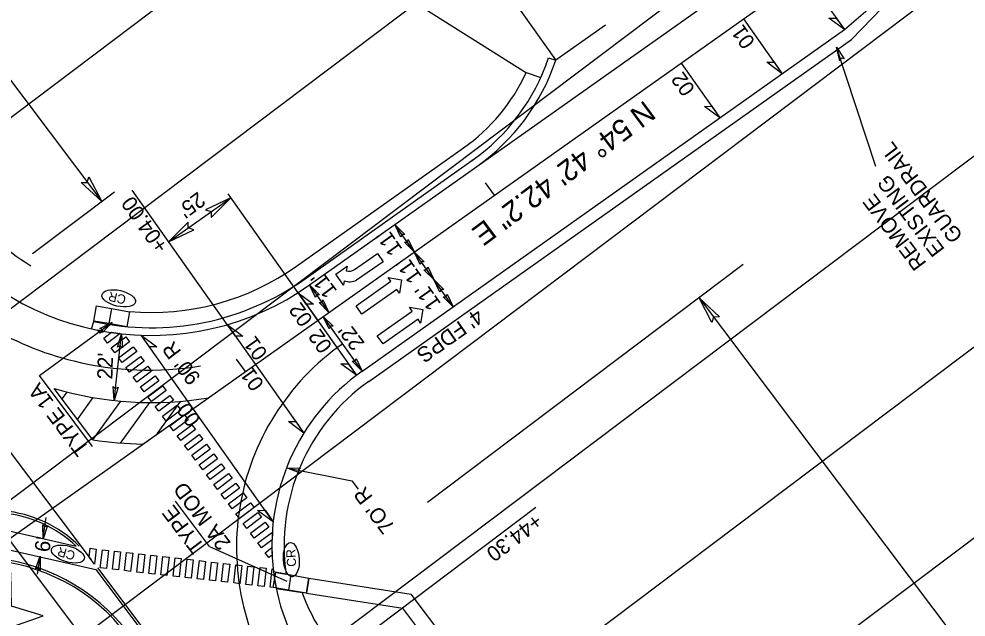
# Model space of a CAD drawing. Extents: x 1262309 to 1264352, y 775189 to 777755.
# Drawn here: x 1263383.2 to 1263693.6, y 776538.6 to 776734.6 of the extents above; entities that cross this region are included whole.
import ezdxf

# ---------------------------------------------------------------- set-up
doc = ezdxf.new("R2010")
doc.units = 0
for name, color, linetype in [('Default', 7, 'Continuous'), ('Old_Level_2', 7, 'Continuous'), ('Prop Conc 2ft 6in Curb and Gutter', 7, 'Continuous'), ('Prop Conc 4in Sidewalk', 7, 'Continuous'), ('Prop Conc 5in Monolithic Keyed In Island', 7, 'Continuous'), ('Prop Dimension', 7, 'Continuous'), ('Prop Dimension Text', 7, 'Continuous'), ('Prop EOT', 7, 'Continuous'), ('Prop Horizontal Alignment', 7, 'Continuous'), ('Prop Horizontal Alignment Direction Label', 7, 'Continuous'), ('Prop Horizontal Alignment Tick Small', 7, 'Continuous'), ('Prop Lane Arrow CELL', 7, 'Continuous'), ('Prop Lane Lines', 7, 'Continuous'), ('Prop Mkg Solid White Crosswalks', 7, 'Continuous'), ('Prop Paint Stripe', 7, 'Continuous'), ('Prop Paved Shoulder', 7, 'Continuous'), ('Prop RDY Traffic Signal CELL', 7, 'Continuous'), ('Prop Superelevation  Arrow CELL', 7, 'Continuous'), ('Prop Superelevation Label', 7, 'Continuous'), ('Prop Terminator CELL', 7, 'Continuous'), ('Scratch_Level_3', 7, 'Continuous'), ('Scratch_Level_5', 7, 'Continuous')]:
    doc.layers.add(name, color=color, linetype=linetype)

msp = doc.modelspace()

# ---------------------------------------------------------------- linework, layer by layer
at = {"layer": 'Default'}
for centre, major_axis in [((1263415.87, 776643.06), (-5.47, 1.25)), ((1263399.22, 776559.25), (-5.38, 1.6)), ((1263472.45, 776557.44), (-0.35, 5.6))]:
    msp.add_ellipse(centre, major_axis=major_axis, ratio=0.462467, dxfattribs=at)
at = {"layer": 'Old_Level_2'}
for p, q in [((1263407.74, 776635.62), (1263408.59, 776640.54)), ((1263408.59, 776640.54), (1263413.51, 776639.69)), ((1263413.51, 776639.69), (1263412.66, 776634.77)), ((1263413.51, 776639.69), (1263419.43, 776638.68)), ((1263419.43, 776638.68), (1263418.58, 776633.75)), ((1263412.66, 776634.77), (1263407.74, 776635.62)), ((1263418.58, 776633.75), (1263412.66, 776634.77)), ((1263466.55, 776548.32), (1263467.4, 776553.24)), ((1263467.4, 776553.24), (1263472.33, 776552.4)), ((1263472.33, 776552.4), (1263471.48, 776547.47)), ((1263472.33, 776552.4), (1263478.24, 776551.38)), ((1263478.24, 776551.38), (1263477.39, 776546.45)), ((1263471.48, 776547.47), (1263466.55, 776548.32)), ((1263477.39, 776546.45), (1263471.48, 776547.47))]:
    msp.add_line(p, q, dxfattribs=at)
at = {"layer": 'Prop Conc 2ft 6in Curb and Gutter'}
for p, q in [((1263556.78, 776721.9), (1263559.15, 776721.1)), ((1263477, 776649.47), (1263534.29, 776690.02)), ((1263406.99, 776633.03), (1263407.7, 776635.43))]:
    msp.add_line(p, q, dxfattribs=at)
for centre, radius, start, end in [((1263492.78, 776743.34), 67.5, 305.2882, 341.4806), ((1263426.45, 776720.9), 87.5, 257.6223, 305.2883)]:
    msp.add_arc(centre, radius, start, end, dxfattribs=at)
at = {"layer": 'Prop Conc 4in Sidewalk'}
for p, q in [((1263549.46, 776717.01), (1263554.21, 776715.37)), ((1263474.11, 776653.56), (1263528.88, 776692.32)), ((1263352.07, 776573.23), (1263401.96, 776561.79)), ((1263357.74, 776565.71), (1263408.37, 776554.17)), ((1263477.39, 776546.45), (1263478.16, 776551.39)), ((1263478.16, 776551.39), (1263511.75, 776546.15)), ((1263482.7, 776550.68), (1263482.7, 776550.68)), ((1263477.39, 776546.45), (1263508.98, 776541.52)), ((1263631.62, 776387.01), (1263511.75, 776546.15)), ((1263627.63, 776384), (1263508.98, 776541.52))]:
    msp.add_line(p, q, dxfattribs=at)
for centre, radius, start, end in [((1263492.78, 776743.34), 62.5, 305.2882, 335.0887), ((1263426.45, 776720.9), 82.5, 265.1157, 305.2883)]:
    msp.add_arc(centre, radius, start, end, dxfattribs=at)
at = {"layer": 'Prop Conc 5in Monolithic Keyed In Island'}
msp.add_line((1263408.37, 776554.17), (1263476.42, 776463.84), dxfattribs=at)
for centre, radius, start, end in [((1263374.37, 776532.83), 40, 46.384, 84.7486), ((1263368.91, 776495.2), 63, 36.9874, 86.8533)]:
    msp.add_arc(centre, radius, start, end, dxfattribs=at)
at = {"layer": 'Prop Dimension'}
for p, q in [((1263199.74, 776954.3), (1263410.31, 776674.73)), ((1263531.55, 776760.08), (1263559.04, 776721.24)), ((1263451.43, 776634.43), (1263420.26, 776678.47)), ((1263432.22, 776661.58), (1263452.62, 776676.02)), ((1263474.65, 776644.89), (1263451.74, 776677.26)), ((1263512.77, 776658.25), (1263506.42, 776667.23)), ((1263519.18, 776649.2), (1263512.77, 776658.25)), ((1263620.57, 776654.09), (1263517.13, 776576.18)), ((1263525.48, 776640.3), (1263519.18, 776649.2)), ((1263606.13, 776643.21), (1263816.71, 776363.63)), ((1263495.65, 776619.18), (1263482.94, 776637.14)), ((1263414.4, 776609.55), (1263416.77, 776631.42)), ((1263470.88, 776587.53), (1263492.31, 776583.24)), ((1263492.31, 776583.24), (1263494.35, 776580.54)), ((1263552.6, 776574.48), (1263437.44, 776487.74)), ((1263391.18, 776565.46), (1263392.08, 776571.21)), ((1263389.21, 776552.68), (1263390.1, 776558.41))]:
    msp.add_line(p, q, dxfattribs=at)
at = {"layer": 'Prop Dimension Text'}
for p, q in [((1263509.79, 776742.02), (1263549.53, 776716.98)), ((1263414.46, 776677.86), (1263387.59, 776657.62)), ((1263478.44, 776647.43), (1263484.8, 776638.46)), ((1263389.86, 776617.77), (1263413.72, 776635.21)), ((1263407.33, 776594.49), (1263389.86, 776617.77)), ((1263445.65, 776561.73), (1263434.5, 776576.6)), ((1263445.65, 776561.73), (1263470.95, 776550.38))]:
    msp.add_line(p, q, dxfattribs=at)
msp.add_lwpolyline([(1263664.08, 776686.26), (1263651.21, 776725.38)], dxfattribs=at)
for points in [[(1263406.13, 776682.85), (1263410.31, 776674.73), (1263403.59, 776681), (1263405.56, 776681.04)], [(1263446.17, 776669.55), (1263452.62, 776676.02), (1263444.31, 776672.1), (1263446.17, 776671.45)], [(1263438.67, 776668.04), (1263432.22, 776661.58), (1263440.53, 776665.5), (1263438.67, 776666.14)], [(1263610.3, 776635.09), (1263606.13, 776643.21), (1263612.85, 776636.94), (1263610.88, 776636.9)], [(1263409.65, 776633.15), (1263413.72, 776635.21), (1263410.57, 776631.87), (1263410.55, 776632.85)]]:
    msp.add_lwpolyline(points, close=True, dxfattribs=at)
at = {"layer": 'Prop EOT'}
for p, q in [((1263653.77, 776731.09), (1263672.75, 776747.55)), ((1263575.42, 776732.61), (1263559.15, 776721.1)), ((1263495.54, 776619.1), (1263653.77, 776731.09)), ((1263478.44, 776647.43), (1263533.22, 776686.2)), ((1263408.87, 776554.75), (1263477.01, 776464.29))]:
    msp.add_line(p, q, dxfattribs=at)
for centre, radius, start, end in [((1263492.78, 776743.34), 70, 305.2882, 341.4806), ((1263426.45, 776720.9), 90, 216.9873, 305.2883), ((1263536.09, 776562.04), 70, 125.4009, 187.1062), ((1263374.37, 776532.83), 40.75, 45.4749, 84.7486), ((1263368.91, 776495.2), 62.25, 36.9874, 86.8533), ((1263536.09, 776562.04), 70, 187.1062, 216.9874)]:
    msp.add_arc(centre, radius, start, end, dxfattribs=at)
at = {"layer": 'Prop Horizontal Alignment'}
for p, q in [((1263049.28, 776330.22), (1263743.09, 776821.26)), ((1263830.93, 775965.32), (1263334.24, 776624.75))]:
    msp.add_line(p, q, dxfattribs=at)
at = {"layer": 'Prop Horizontal Alignment Tick Small'}
for p, q in [((1263539.03, 776676.84), (1263536.14, 776680.92)), ((1263457.4, 776619.07), (1263454.52, 776623.15))]:
    msp.add_line(p, q, dxfattribs=at)
at = {"layer": 'Prop Lane Arrow CELL'}
for p, q in [((1263493.15, 776652.55), (1263500.7, 776657.72)), ((1263500.7, 776657.72), (1263502.56, 776654.99)), ((1263502.56, 776654.99), (1263493.85, 776649.04)), ((1263487.02, 776650.96), (1263490.71, 776653.55)), ((1263489.55, 776647.36), (1263487.02, 776650.96)), ((1263490.71, 776653.55), (1263490.43, 776652.09)), ((1263489.82, 776648.82), (1263489.55, 776647.36)), ((1263493.69, 776640.56), (1263505.12, 776648.65)), ((1263505.12, 776648.65), (1263504.25, 776649.88)), ((1263504.25, 776649.88), (1263508.61, 776649.16)), ((1263508.61, 776649.16), (1263507.89, 776644.73)), ((1263507.02, 776645.96), (1263495.6, 776637.87)), ((1263507.89, 776644.73), (1263507.02, 776645.96)), ((1263495.6, 776637.87), (1263493.69, 776640.56)), ((1263500.64, 776630.79), (1263512.07, 776638.88)), ((1263512.07, 776638.88), (1263511.21, 776640.11)), ((1263511.21, 776640.11), (1263515.57, 776639.4)), ((1263515.57, 776639.4), (1263514.85, 776634.96)), ((1263513.98, 776636.19), (1263502.55, 776628.1)), ((1263514.85, 776634.96), (1263513.98, 776636.19)), ((1263502.55, 776628.1), (1263500.64, 776630.79))]:
    msp.add_line(p, q, dxfattribs=at)
for centre, radius, start, end in [((1263491.3, 776655.23), 3.27, 254.7199, 304.378), ((1263491.58, 776653.75), 5.25, 250.3903, 295.702)]:
    msp.add_arc(centre, radius, start, end, dxfattribs=at)
at = {"layer": 'Prop Lane Lines'}
for p, q in [((1263533.22, 776686.2), (1263634.71, 776758.03)), ((1263406.92, 776557.35), (1263369.15, 776607.49))]:
    msp.add_line(p, q, dxfattribs=at)
for centre, radius, start, end in [((1263424.65, 776719.73), 100, 220.0607, 256.4057), ((1263535.98, 776561.36), 81.5, 124.947, 216.6462), ((1263425.74, 776721.01), 101.5, 255.9734, 279.6349)]:
    msp.add_arc(centre, radius, start, end, dxfattribs=at)
at = {"layer": 'Prop Mkg Solid White Crosswalks'}
for points in [[(1263410.78, 776632.35), (1263409.76, 776631.59), (1263408.93, 776632.7)], [(1263416.36, 776631.55), (1263412.17, 776628.39), (1263410.97, 776629.99), (1263413.52, 776631.91)], [(1263418.16, 776630.4), (1263419.37, 776628.81), (1263414.58, 776625.2), (1263413.37, 776626.79)], [(1263420.57, 776627.21), (1263421.77, 776625.61), (1263416.98, 776622), (1263415.78, 776623.6)], [(1263422.98, 776624.01), (1263424.18, 776622.42), (1263419.39, 776618.81), (1263418.19, 776620.4)], [(1263425.38, 776620.82), (1263426.59, 776619.22), (1263421.8, 776615.61), (1263420.59, 776617.21)], [(1263427.79, 776617.62), (1263428.99, 776616.03), (1263424.2, 776612.42), (1263423, 776614.01)], [(1263430.2, 776614.43), (1263431.4, 776612.83), (1263426.61, 776609.22), (1263425.41, 776610.82)], [(1263432.6, 776611.23), (1263433.81, 776609.64), (1263429.01, 776606.03), (1263427.81, 776607.62)], [(1263435.01, 776608.04), (1263436.21, 776606.44), (1263431.42, 776602.83), (1263430.22, 776604.43)], [(1263437.42, 776604.84), (1263438.62, 776603.25), (1263433.83, 776599.64), (1263432.62, 776601.23)], [(1263439.82, 776601.65), (1263441.03, 776600.05), (1263436.23, 776596.44), (1263435.03, 776598.04)], [(1263442.23, 776598.45), (1263443.43, 776596.85), (1263438.64, 776593.25), (1263437.44, 776594.84)], [(1263444.64, 776595.26), (1263445.84, 776593.66), (1263441.05, 776590.05), (1263439.84, 776591.65)], [(1263447.04, 776592.06), (1263448.25, 776590.46), (1263443.45, 776586.85), (1263442.25, 776588.45)], [(1263449.45, 776588.87), (1263450.65, 776587.27), (1263445.86, 776583.66), (1263444.66, 776585.26)], [(1263451.86, 776585.67), (1263453.06, 776584.07), (1263448.27, 776580.46), (1263447.06, 776582.06)], [(1263454.26, 776582.48), (1263455.47, 776580.88), (1263450.67, 776577.27), (1263449.47, 776578.87)], [(1263456.67, 776579.28), (1263457.87, 776577.68), (1263453.08, 776574.07), (1263451.88, 776575.67)], [(1263459.08, 776576.09), (1263460.28, 776574.49), (1263455.49, 776570.88), (1263454.28, 776572.48)], [(1263461.48, 776572.89), (1263462.69, 776571.29), (1263457.89, 776567.68), (1263456.69, 776569.28)], [(1263463.89, 776569.7), (1263465.09, 776568.1), (1263460.3, 776564.49), (1263459.1, 776566.09)], [(1263466.12, 776563.87), (1263462.7, 776561.29), (1263461.5, 776562.89), (1263466.24, 776566.46)], [(1263408.53, 776560.9), (1263407.97, 776555.95), (1263406.22, 776558.25), (1263406.54, 776561.13)], [(1263465.11, 776558.1), (1263463.91, 776559.7), (1263466.1, 776561.35), (1263466.17, 776558.89)], [(1263410.52, 776560.68), (1263412.5, 776560.45), (1263411.83, 776554.49), (1263409.84, 776554.72)], [(1263414.49, 776560.23), (1263416.48, 776560.01), (1263415.81, 776554.04), (1263413.82, 776554.27)], [(1263418.47, 776559.78), (1263420.45, 776559.56), (1263419.78, 776553.59), (1263417.79, 776553.82)], [(1263422.44, 776559.33), (1263424.43, 776559.11), (1263423.76, 776553.15), (1263421.77, 776553.37)], [(1263426.42, 776558.88), (1263428.4, 776558.66), (1263427.73, 776552.7), (1263425.74, 776552.92)], [(1263430.39, 776558.43), (1263432.38, 776558.21), (1263431.7, 776552.25), (1263429.72, 776552.47)], [(1263434.37, 776557.98), (1263436.35, 776557.76), (1263435.68, 776551.8), (1263433.69, 776552.02)], [(1263438.34, 776557.54), (1263440.33, 776557.31), (1263439.65, 776551.35), (1263437.67, 776551.57)], [(1263442.31, 776557.09), (1263444.3, 776556.86), (1263443.63, 776550.9), (1263441.64, 776551.12)], [(1263446.29, 776556.64), (1263448.28, 776556.41), (1263447.6, 776550.45), (1263445.62, 776550.67)], [(1263450.26, 776556.19), (1263452.25, 776555.96), (1263451.58, 776550), (1263449.59, 776550.23)], [(1263454.24, 776555.74), (1263456.23, 776555.51), (1263455.55, 776549.55), (1263453.57, 776549.78)], [(1263458.21, 776555.29), (1263460.2, 776555.06), (1263459.53, 776549.1), (1263457.54, 776549.33)], [(1263462.19, 776554.84), (1263464.18, 776554.62), (1263463.5, 776548.65), (1263461.51, 776548.88)], [(1263467.48, 776548.2), (1263465.49, 776548.43), (1263466.16, 776554.39), (1263466.52, 776554.35), (1263466.72, 776552.69), (1263466.88, 776551.57), (1263467.3, 776549.09)]]:
    msp.add_lwpolyline(points, close=True, dxfattribs=at)
at = {"layer": 'Prop Paint Stripe'}
for p, q in [((1263407.42, 776596.7), (1263394.76, 776613.47)), ((1263397.33, 776610.07), (1263398.95, 776612.33)), ((1263402.37, 776603.38), (1263407.5, 776610.51)), ((1263407.42, 776596.7), (1263416.52, 776609.34)), ((1263416.51, 776595.64), (1263426.06, 776608.9)), ((1263423.79, 776595.28), (1263445.29, 776610.49)), ((1263428.52, 776598.62), (1263436.22, 776609.32))]:
    msp.add_line(p, q, dxfattribs=at)
for radius, start, end in [(112, 253.5627, 279.6822), (125.65, 261.2866, 268.7859)]:
    msp.add_arc((1263426.45, 776720.9), radius, start, end, dxfattribs=at)
at = {"layer": 'Prop Paved Shoulder'}
for p, q in [((1263673.7, 776746.21), (1263656.08, 776727.82)), ((1263497.85, 776615.84), (1263656.08, 776727.82)), ((1263470.76, 776552.67), (1263466.62, 776553.38)), ((1263467.51, 776547.99), (1263475.96, 776546.7))]:
    msp.add_line(p, q, dxfattribs=at)
for centre, radius, start, end in [((1263434.28, 776730.38), 90, 218.8085, 238.3878), ((1263536.09, 776562.04), 66, 125.4009, 188.1683), ((1263532.48, 776566.84), 60, 199.6151, 216.9874)]:
    msp.add_arc(centre, radius, start, end, dxfattribs=at)
at = {"layer": 'Prop RDY Traffic Signal CELL'}
msp.add_lwpolyline([(1263374.48, 776533.24), (1263381.03, 776524.55), (1263380.84, 776535.43), (1263391.15, 776538.98), (1263380.72, 776542.17), (1263380.53, 776553.06), (1263374.28, 776544.14), (1263363.87, 776547.32), (1263370.42, 776538.63), (1263364.17, 776529.69), (1263374.48, 776533.24)], dxfattribs=at)
at = {"layer": 'Prop Superelevation  Arrow CELL'}
for p, q in [((1263641.07, 776749.04), (1263653.77, 776731.09)), ((1263620.66, 776734.6), (1263633.36, 776716.65)), ((1263600.25, 776720.16), (1263612.96, 776702.21)), ((1263474.65, 776644.89), (1263481.08, 776635.82)), ((1263481.05, 776635.85), (1263493.81, 776617.83)), ((1263451.43, 776634.43), (1263460.67, 776621.38)), ((1263466.52, 776569.83), (1263423.26, 776630.95)), ((1263460.67, 776621.38), (1263476.58, 776598.9))]:
    msp.add_line(p, q, dxfattribs=at)
for points in [[(1263653.77, 776731.09), (1263648.67, 776734.83), (1263651.1, 776734.86)], [(1263633.36, 776716.65), (1263628.27, 776720.39), (1263630.69, 776720.42)], [(1263612.96, 776702.21), (1263607.86, 776705.95), (1263610.29, 776705.98)], [(1263474.65, 776644.89), (1263479.75, 776641.15), (1263477.33, 776641.12)], [(1263451.43, 776634.43), (1263456.53, 776630.69), (1263454.11, 776630.65)], [(1263423.26, 776630.95), (1263428.36, 776627.21), (1263425.94, 776627.18)], [(1263493.81, 776617.83), (1263488.71, 776621.57), (1263491.13, 776621.61)], [(1263476.58, 776598.9), (1263471.48, 776602.64), (1263473.9, 776602.68)], [(1263466.52, 776569.83), (1263461.42, 776573.57), (1263463.85, 776573.61)]]:
    msp.add_lwpolyline(points, close=True, dxfattribs=at)
at = {"layer": 'Prop Terminator CELL'}
for points in [[(1263652.21, 776720.92), (1263651.21, 776725.38), (1263653.68, 776721.5), (1263652.72, 776721.73)], [(1263508.38, 776663.11), (1263506.42, 776667.23), (1263509.68, 776664), (1263508.7, 776664.01)], [(1263510.8, 776662.37), (1263512.77, 776658.25), (1263509.5, 776661.48), (1263510.49, 776661.48)], [(1263514.74, 776654.13), (1263512.77, 776658.25), (1263516.04, 776655.02), (1263515.05, 776655.03)], [(1263517.21, 776653.32), (1263519.18, 776649.2), (1263515.91, 776652.43), (1263516.9, 776652.43)], [(1263521.14, 776645.08), (1263519.18, 776649.2), (1263522.44, 776645.97), (1263521.46, 776645.98)], [(1263480.41, 776643.31), (1263478.44, 776647.43), (1263481.71, 776644.2), (1263480.73, 776644.21)], [(1263482.83, 776642.58), (1263484.8, 776638.46), (1263481.53, 776641.69), (1263482.52, 776641.68)], [(1263523.51, 776644.42), (1263525.48, 776640.3), (1263522.21, 776643.53), (1263523.2, 776643.52)], [(1263484.91, 776633.02), (1263482.94, 776637.14), (1263486.21, 776633.91), (1263485.22, 776633.92)], [(1263415.51, 776627.03), (1263416.77, 776631.42), (1263417.08, 776626.84), (1263416.34, 776627.49)], [(1263493.68, 776623.3), (1263495.65, 776619.18), (1263492.38, 776622.41), (1263493.37, 776622.41)], [(1263415.66, 776613.94), (1263414.4, 776609.55), (1263414.09, 776614.13), (1263414.83, 776613.47)], [(1263475.14, 776585.89), (1263470.88, 776587.53), (1263475.48, 776587.42), (1263474.75, 776586.75)], [(1263392.54, 776568.61), (1263391.08, 776564.28), (1263390.99, 776568.87), (1263391.69, 776568.18)], [(1263388.62, 776554.26), (1263390.08, 776558.59), (1263390.18, 776553.99), (1263389.47, 776554.69)]]:
    msp.add_lwpolyline(points, close=True, dxfattribs=at)
at = {"layer": 'Scratch_Level_3'}
for p, q in [((1263115.74, 776502.96), (1263610.84, 776875.88)), ((1263145.82, 776463.02), (1263640.93, 776835.94)), ((1263175.91, 776423.09), (1263671.01, 776796)), ((1263205.99, 776383.15), (1263701.09, 776756.06)), ((1263236.07, 776343.21), (1263731.17, 776716.12)), ((1263266.15, 776303.27), (1263761.25, 776676.19)), ((1263296.23, 776263.33), (1263791.33, 776636.25))]:
    msp.add_line(p, q, dxfattribs=at)
at = {"layer": 'Scratch_Level_5'}
msp.add_line((1263475.3, 776643.98), (1263486.85, 776627.66), dxfattribs=at)

# ---------------------------------------------------------------- texts
at = {"layer": 'Default'}
for rotation, p in [(167.1185, (1263418.5, 776643.97)), (163.4716, (1263401.9, 776560)), (93.5483, (1263474.07, 776555.18))]:
    msp.add_text('CR', height=3, rotation=rotation, dxfattribs=at).set_placement(p)
at = {"layer": 'Prop Dimension'}
for s, rotation, p in [("11'", 125.2883, (1263509.05, 776659.19)), ("11'", 125.2883, (1263515.45, 776650.14)), ("11'", 125.2883, (1263521.7, 776641.31)), ("22'", 126.9874, (1263496.71, 776628.37)), ("90' R", 127.0213, (1263442.97, 776617.12)), ("22'", 88.4483, (1263413.8, 776616.43)), ('TYPE 1A', 127.0213, (1263406.43, 776593.8)), ('2A MOD', 127.0213, (1263452.82, 776562.92)), ("7O' R", 127.0213, (1263506.64, 776568.3)), ('TYPE ', 127.0213, (1263444.25, 776561.83)), ("6'", 81.4269, (1263393.13, 776559.64))]:
    msp.add_text(s, height=5, rotation=rotation, dxfattribs=at).set_placement(p)
at = {"layer": 'Prop Dimension Text'}
for s, rotation, p in [('GUARDRAIL', 126.9874, (1263692.84, 776663.59)), ('EXISTING', 126.9874, (1263686.84, 776659.08)), ('+04.00', 125.2883, (1263432.39, 776660.15)), ("25'", 216.5764, (1263441.86, 776678.19)), ('REMOVE', 126.9874, (1263680.85, 776654.57)), ("11'", 127.2624, (1263487.68, 776645.49)), ("4' FDPS", 215.2883, (1263533.2, 776639.92)), ('+44.30', 216.9874, (1263552.39, 776572.81))]:
    msp.add_text(s, height=5, rotation=rotation, dxfattribs=at).set_placement(p)
at = {"layer": 'Prop Horizontal Alignment Direction Label'}
msp.add_text('N 54%%d 42\' 42.2" E', height=7, rotation=216.7269, dxfattribs=at).set_placement((1263588.31, 776708.15))
at = {"layer": 'Prop Superelevation Label'}
for s, p in [('01', (1263624.7, 776727.1)), ('02', (1263605.01, 776711.64)), ('02', (1263479.73, 776636.09)), ('02', (1263486.08, 776627.38)), ('01', (1263464.9, 776625.04)), ('01', (1263463.75, 776614.99)), ('00', (1263442.95, 776603.31))]:
    msp.add_text(s, height=5, rotation=125.2883, dxfattribs=at).set_placement(p)

doc.saveas('drawing.dxf')
